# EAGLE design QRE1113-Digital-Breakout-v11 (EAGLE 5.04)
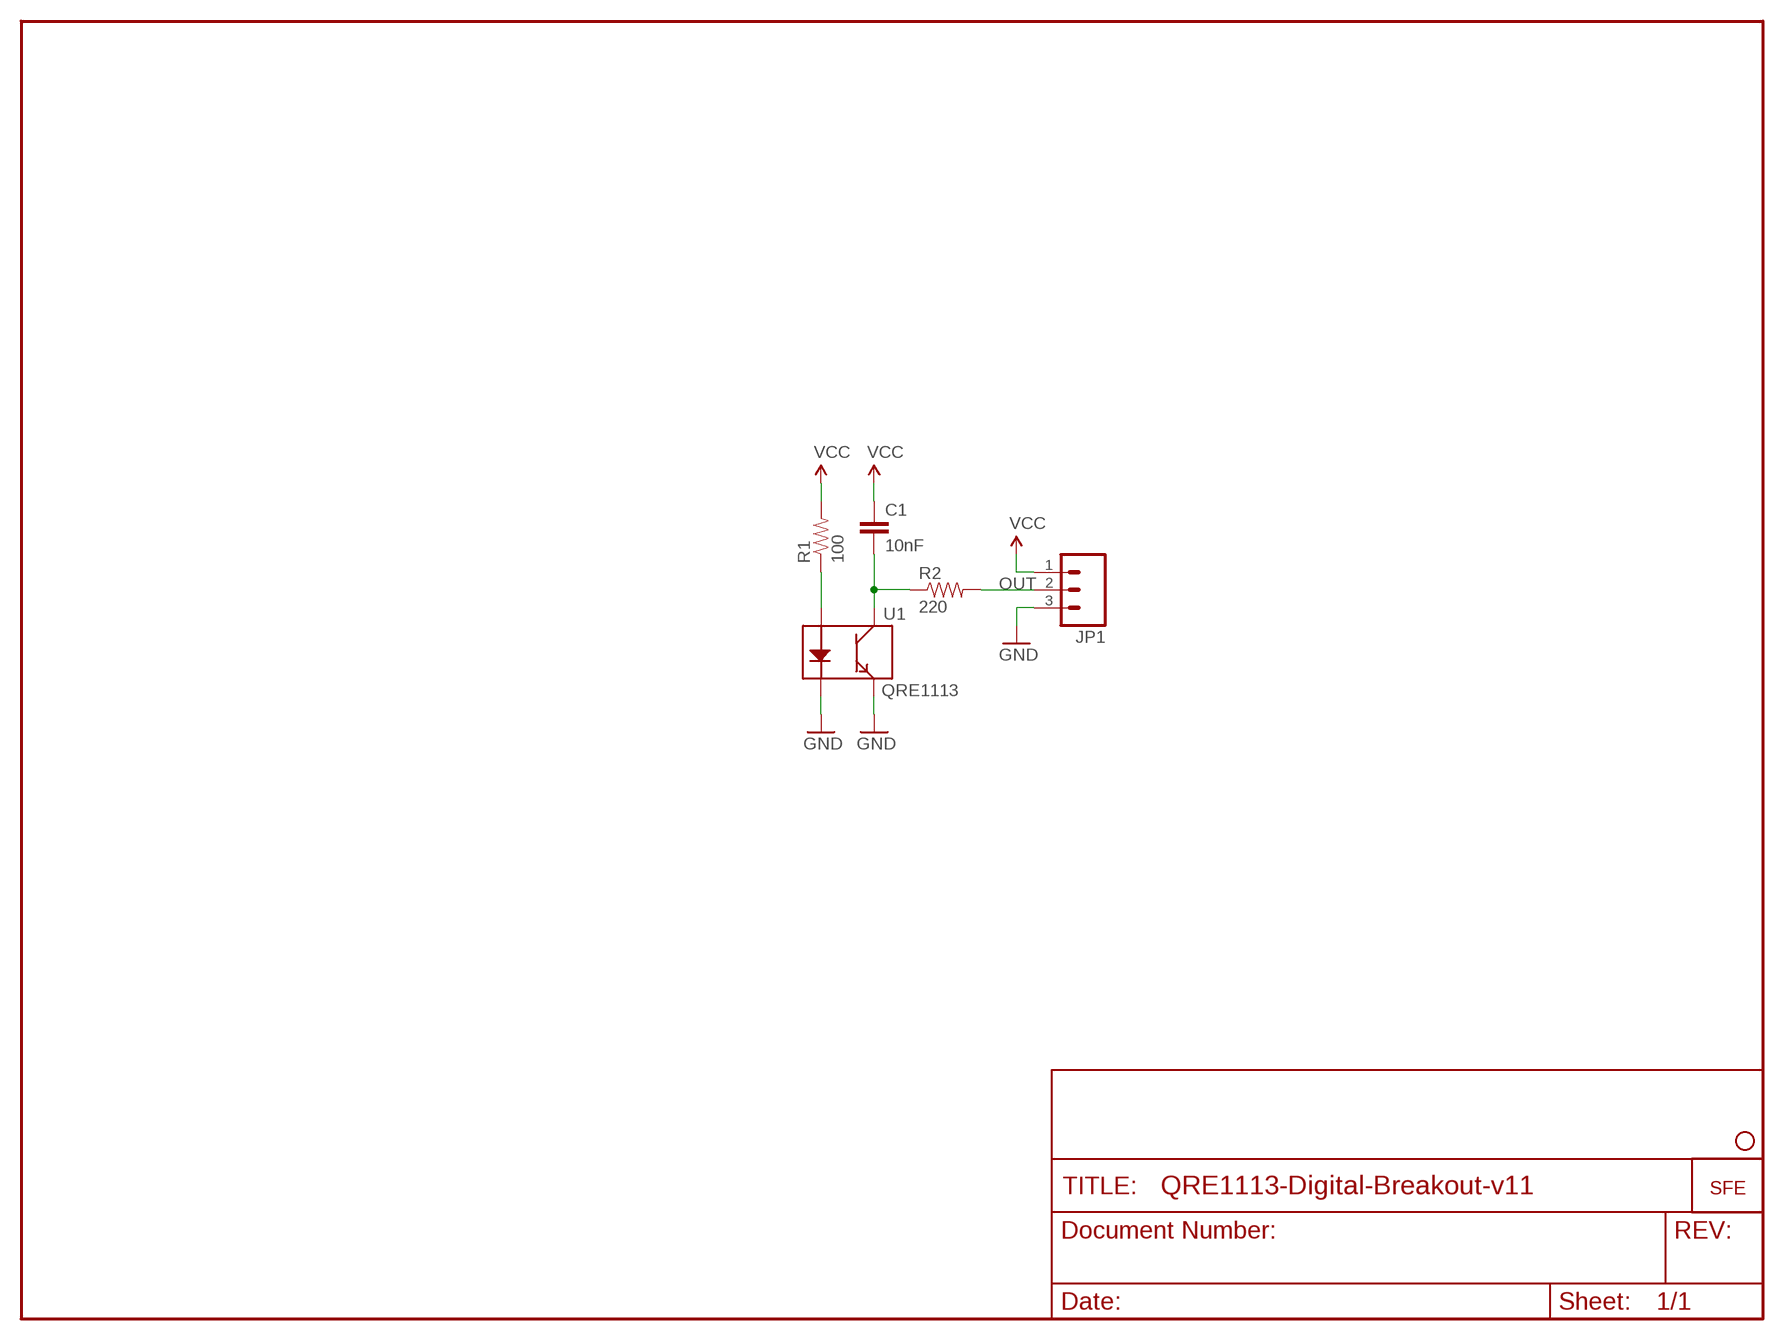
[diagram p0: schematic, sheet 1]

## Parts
C1  10nF  CAP0402-CAP  [0402-CAP]
JP1  M03PTH  [1X03]
JP2  LOGO-SFESK  [SFE-LOGO-FLAME]
JP3  STAND-OFF  [STAND-OFF]
R1  100  RESISTOR0402-RES  [0402-RES]
R2  220  RESISTOR0402-RES  [0402-RES]
U1  QRE1113  [QRE1113]

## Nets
GND: JP1.3 U1.2(K) U1.4(E)
N$1: R1.1 U1.1(A)
OUT: JP1.2 R2.2
OUT1: C1.2 R2.1 U1.3(C)
VCC: C1.1 JP1.1 R1.2

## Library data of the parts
C1 = SparkFun:CAP: Capacitor
JP1 = SparkFun:M03: Header 3 Standard 3-pin 0.1" header. Use with straight break away headers (SKU : PRT-00116), right angle break away headers (PRT-00553), swiss pins (PRT-00743), machine pins (PRT-00117), and female headers (PRT-00115). Molex polarized connector foot print use with SKU : PRT-08232 with associated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
JP2 = SparkFun:LOGO-SFE: Spark Fun Electronics PCB Logo
JP3 = SparkFun:STAND-OFF: Stand Off
R1 R2 = SparkFun:RESISTOR: Resistor
U1 = SparkFun:QRE1113

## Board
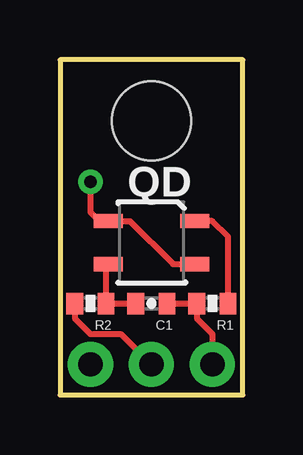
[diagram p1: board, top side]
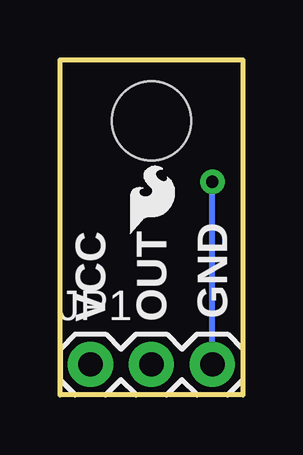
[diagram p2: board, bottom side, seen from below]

Size 7.62 x 13.97 mm. Coordinates in mm from the lower left corner, seen from the top.
Outline: 0,0 7.62,0 7.62,13.97 0,13.97 0,0
Copper layers (1*16): Top 0.035mm / dielectric 1.5mm / Bottom 0.035mm
Design rules "SparkFun": minimum track width 8mil, minimum drill 20mil, track to track 8mil, track to pad 8mil, pad to pad 8mil, via to via 8mil, smd to smd 8mil, copper to edge 9mil, drill to drill 8mil, minimum pad ring 12mil, minimum via ring 10mil, stop-mask expansion 4mil, vias tented up to drill 20mil, thermal gap 10mil

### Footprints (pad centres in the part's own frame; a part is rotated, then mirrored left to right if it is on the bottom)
0402-CAP = smd 0.7 x 0.9: 1 -0.65,0; 2 0.65,0
1X03 = drill 1.016 pad 1.88 round: 1 0,0; 2 2.54,0; 3 5.08,0
STAND-OFF = hole 3.302: 0,0
0402-RES = smd 0.7 x 0.9: 1 -0.65,0; 2 0.65,0
QRE1113 = smd 1.2 x 0.6: 1 -1.8,-0.9; 2 1.8,-0.9; 3 1.8,0.9; 4 -1.8,0.9

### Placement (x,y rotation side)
C1  3.81,3.81 180 top
JP1  6.35,1.27 0 bottom
JP2  4.7,6.73 0 bottom
JP3  3.81,11.43 0 top
R1  6.35,3.81 180 top
R2  1.27,3.81 180 top
U1  3.81,6.35 180 top

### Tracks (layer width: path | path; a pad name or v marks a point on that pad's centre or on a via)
GND  (via drill 0.51)
  Top 0.254: U1.4 4.71,5.45 2.91,7.25 U1.2 1.64,7.25 1.27,7.62 v1.27,8.89
  Bottom 0.254: JP1.3 v1.27,8.89
N$1
  Top 0.254: U1.1 6.35,7.25 7,6.6 R1.1
OUT
  Top 0.254: R2.2 0.62,3.19 1.27,2.54 2.54,2.54 JP1.2
OUT1
  Top 0.254: C1.2 R2.1 1.92,5.36 U1.3
VCC
  Top 0.254: C1.1 R1.2 5.7,3.19 6.35,2.54 JP1.1

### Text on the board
tPlace: QD
bPlace: GND | OUT | VCC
